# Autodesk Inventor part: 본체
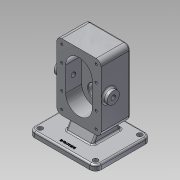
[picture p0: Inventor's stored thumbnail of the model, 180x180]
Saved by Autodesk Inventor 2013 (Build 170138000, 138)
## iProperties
Created: 2020-04
Part Number: 본체
Material: 알루미늄 6061
Document SubType Name: Modeling
Designer: default
Density: 2.71 g/cm^3
Mass: 1477.95 g
Surface Area: 818.192 cm^2
Volume: 545.37 cm^3
Author: default
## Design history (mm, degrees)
sketch "스케치1"
  geometry: L1 (31, -60)-(-31, -60); L2 (-40, -51)-(-40, 51); L3 (-31, 60)-(31, 60); L4 (40, 51)-(40, -51); L5 (40, -60)-(-40, 60); L6 (-40, -60)-(40, 60); A1 r 9 centre (-31, 51) between (-31, 60) and (-40, 51); A2 r 9 centre (31, 51) between (40, 51) and (31, 60); A3 r 9 centre (-31, -51) between (-40, -51) and (-31, -60); A4 r 9 centre (31, -51) between (31, -60) and (40, -51); 1 further point
  constraints: 12 end point, 8 point on circle, 8 point on line, 8 tangent, 4 centre point, 3 equal radius, 2 midpoint, 2 parallel, 1 horizontal, 1 perpendicular
  dimensions: "d0" = 80 distance of L5.end L6.end; "d1" = 120 distance of L6.start L5.end; "d2" = 9 radius of A1
extrude "돌출1" new body sketch "스케치1" stored distance "d3" = 53; taper "d4" = 0 deg
sketch "스케치2"
  geometry: L1 (40, -51)-(40, 51) reference; L2 (24, 22)-(24, 0); L3 (-24, 22)-(-24, 0); L4 (0, 0)-(-24, 0); L5 (0, 0)-(24, 0); L6 (24, -22)-(24, 0); L7 (-24, -22)-(-24, 0); A1 r 24 centre (0, 22) between (24, 22) and (-24, 22); A2 r 24 centre (0, -22) between (-24, -22) and (24, -22)
  constraints: 12 end point, 4 point on circle, 3 symmetric about line, 2 centre point, 2 perpendicular, 2 tangent, 1 collinear, 1 other
  dimensions: "d6" = 48 diameter of A1; "d8" = 22 distance of L2.start L2.end
extrude "돌출2" cut sketch "스케치2" distance "d9" = 29; taper "d10" = 0 deg
sketch "스케치4"
  geometry: L1 (24, -22)-(24, 22) reference; L2 (-24, 22)-(-24, -22) reference; C1 r 19 at (0, 22); A1 r 24 centre (0, -22) between (-24, -22) and (24, -22) reference; A2 r 24 centre (0, 22) between (24, 22) and (-24, 22) reference; 1 further point
  constraints: 1 centre point, 1 coincident
  dimensions: "d11" = 38 diameter of C1
extrude "돌출3" join sketch "스케치4" distance "d12" = 17; taper "d13" = 0 deg
sketch "스케치5"
  geometry: L1 (3, -43.5)-(41, -43.5); L2 (41, -26.5)-(3, -26.5); L3 (51, 26.5)-(51, -26.5) reference; L4 (60, 26.5)-(51, 26.5) reference; L5 (60, -26.5)-(60, 26.5) reference; L6 (51, -26.5)-(60, -26.5) reference; L7 (-51, 26.5)-(-51, -26.5) reference; L8 (51, 26.5)-(-51, 26.5) reference; L9 (51, 26.5)-(51, -26.5) reference; L10 (-51, -26.5)-(51, -26.5) reference; L11 (22, 26.5)-(22, 26.5) reference; L12 (22, 26.5)-(22, -2.5) reference; L13 (22, -2.5)-(22, -2.5) reference; L14 (22, 26.5)-(22, -2.5) reference; L15 (22, -2.5)-(46, -2.5) reference; L16 (22, -43.5)-(22, 50.532); L17 (22, -2.5)-(34.5, -2.5); L18 (34.5, -2.5)-(34.5, -17.5); L19 (34.5, -17.5)-(22, -17.5); L20 (22, -17.5)-(22, -2.5); L21 (22, -17.5)-(30.5, -17.5); L22 (30.5, -17.5)-(30.5, -36.2); L23 (30.5, -36.2)-(22, -36.2); L24 (22, -36.2)-(22, -17.5); L25 (22, -36.2)-(36, -36.2); L26 (36, -36.2)-(36, -43.5); L27 (36, -43.5)-(22, -43.5); L28 (22, -43.5)-(22, -36.2); 1 further point
  constraints: 28 end point, 6 parallel, 4 perpendicular, 3 horizontal, 1 midpoint
  dimensions: "d14" = 15 distance of L17.end L18.end; "d16" = 12.5 distance of L18.end L19.end; "d17" = 8.5 distance between parallel lines of L16 L22; "d19" = 14 distance of L26.end L27.end; "d20" = 7.3 distance of L25.end L26.end
revolve "회전1" sketch "스케치5" stored, may be unused: angle "d21" = 90 deg
sketch "스케치6"
  geometry: L1 (40, -51)-(40, 51) reference; L2 (0, 22)-(54.09, 22); L3 (0, 22)-(0, 75.214); L4 (0, 0)-(54.999, 0); A1 r 24 centre (0, 22) between (24, 22) and (-24, 22) reference; A2 r 9 centre (-31, 51) between (-31, 60) and (-40, 51) reference; A3 r 9 centre (31, 51) between (40, 51) and (31, 60) reference; 9 further points
  constraints: 6 end point, 6 symmetric about line, 3 perpendicular, 2 coincident, 1 point on line
hole "구멍1" sketch "스케치6" at (31, 51), (31, 22), (-31, 22), (-31, 51), (-31, -22), (31, -51), (31, -22), (-31, -51) diameter "d22" = 4.134; stored, may be unused: countersink angle "d26" = 90 deg, drill point angle "d28" = 118 deg; dims "d23" = 10, "d24" = 4, "d25" = 2, "d27" = 12
sketch "스케치7"
  geometry: L1 (-22, 26.5)-(-22, -2.5) reference; L2 (-22, -2.5)-(-22, -51.719); L3 (-22, -2.5)-(-9.5, -2.5); L4 (-9.5, -2.5)-(-9.5, -17.5); L5 (-9.5, -17.5)-(-22, -17.5); L6 (-22, -17.5)-(-22, -2.5); 1 further point
  constraints: 10 end point, 2 parallel, 1 collinear, 1 horizontal, 1 perpendicular
  dimensions: "d29" = 12.5 distance of L4.end L5.end; "d30" = 15 distance of L3.end L4.end
revolve "회전2" sketch "스케치7" stored, may be unused: angle "d31" = 90 deg
sketch "스케치8"
  geometry: L1 (0, 0)-(0, 102) reference; L2 (53, 102)-(53, 0) reference; L3 (0, 51)-(14, 51); C1 r 11 at (14, 51); 1 further point
  constraints: 2 end point, 1 centre point, 1 coincident, 1 midpoint, 1 perpendicular
  dimensions: "d33" = 14 distance of L3.start L3.end; "d34" = 22 diameter of C1
extrude "돌출4" join sketch "스케치8" distance "d35" = 8; taper "d36" = 0 deg
sketch "스케치9"
  geometry: C1 r 11 at (0, 0) reference; 2 further points
  constraints: 1 coincident
hole "구멍2" sketch "스케치9" at (0, 0) diameter "d37" = 8.376; stored, may be unused: countersink angle "d41" = 90 deg, drill point angle "d43" = 0 deg; dims "d38" = 10, "d39" = 4, "d40" = 2, "d42" = 12
node "작업 평면1"
sketch "스케치10"
  geometry: L1 (-60, -50)-(60, 50); L2 (60, -50)-(-60, 50); L3 (-19, -43.5)-(19, -43.5) reference; L4 (60, -43.5)-(60, 56.5); L5 (60, 56.5)-(-60, 56.5); L6 (-60, 56.5)-(-60, -43.5); L7 (-60, -43.5)-(60, -43.5); 1 further point
  constraints: 12 end point, 2 midpoint, 1 parallel, 1 perpendicular
  dimensions: "d48" = 100 distance of L4.start L4.end; "d49" = 120 distance of L4.end L5.end; "d50" = 100 distance of L5.end L6.end; "d52" = 120 distance of L6.end L4.start (derived)
extrude "돌출5" join sketch "스케치10" distance "d53" = 10; taper "d54" = 0 deg
fillet "모깎기1" dims "d55" = 10
sketch "스케치11"
  geometry: C1 r 4.5 at (-50, 33.5); C2 r 4.5 at (50, 33.5); C3 r 4.5 at (50, -46.5); C4 r 4.5 at (-50, -46.5); A1 r 10 centre (-50, 33.5) between (-50, 43.5) and (-60, 33.5) reference; A2 r 10 centre (-50, -46.5) between (-60, -46.5) and (-50, -56.5) reference; A3 r 10 centre (50, -46.5) between (50, -56.5) and (60, -46.5) reference; A4 r 10 centre (50, 33.5) between (60, 33.5) and (50, 43.5) reference; 1 further point
  constraints: 4 centre point, 4 coincident
  dimensions: "d56" = 9 diameter of C1; "d57" = 9 diameter of C2; "d58" = 9 diameter of C3; "d59" = 9 diameter of C4
extrude "돌출6" cut sketch "스케치11" distance "d60" = 10; taper "d61" = 0 deg
sketch "스케치12"
  geometry: L1 (-60, 26.5)-(-60, -26.5) reference; L2 (-60, -26.5)-(-51, -26.5) reference; L3 (-51, -26.5)-(51, -26.5) reference; L4 (-51, 26.5)-(-60, 26.5) reference; L5 (51, 26.5)-(-51, 26.5) reference; L6 (-80, -33.5)-(-80, 46.5) reference; L7 (-90, -33.5)-(-90, 46.5) reference; L8 (-90, -43.5)-(-90, -33.5) reference; L9 (-80, -33.5)-(-80, -43.5) reference; L10 (-80, -43.5)-(-80, -26.5); L11 (-80, -26.5)-(-54.272, -11.646); L12 (-80, -26.5)-(-80, 26.5); L13 (-80, 26.5)-(-54.272, 11.646); L14 (-54.272, 11.646)-(-54.272, -11.646); 1 further point
  constraints: 10 end point, 2 point on line, 1 parallel
  dimensions: "d62" = 17 distance of L9.end L10.end; "d63" = 120 deg angle of L10 L11; "d64" = 53 distance of L10.end L12.end; "d65" = 60 deg angle of L12 L13
extrude "돌출7" join sketch "스케치12" stored distance "d66" = 48; taper "d67" = 0 deg
fillet "모깎기2" dims "d68" = 3
fillet "모깎기3" dims "d69" = 3
fillet "모깎기4" dims "d70" = 3
fillet "모깎기5" dims "d71" = 3
fillet "모깎기6" dims "d72" = 3
chamfer "모따기1" distance "d73" = 1; stored, may be unused: second distance "d74" = 2, angle "d75" = 45 deg
chamfer "모따기2" distance "d76" = 0.7; stored, may be unused: second distance "d77" = 2, angle "d78" = 30 deg
sketch "스케치14"
  geometry: L1 (-50, -56.5)-(50, -56.5) reference; L2 (60, -46.5)-(60, 33.5) reference; 2 further points
  constraints: 1 other
  dimensions: "d79" = 10 distance from line of L1 point (0, -46.5); "d80" = 60 distance from line of L2 point (0, -46.5)
feature "엠보싱1" sketch "스케치14" dims "d0" = 80, "d1" = 120, "d2" = 9, "d6" = 48, "d8" = 22, "d81" = 0.5, "d82" = 0
fillet "모깎기7" dims "d83" = 0.5
node "솔리드1"
mirror "대칭1"
node "투영된 루프1"
node "투영된 루프3"
node "투영된 루프4"
node "투영된 루프5"
node "투영된 루프6"
